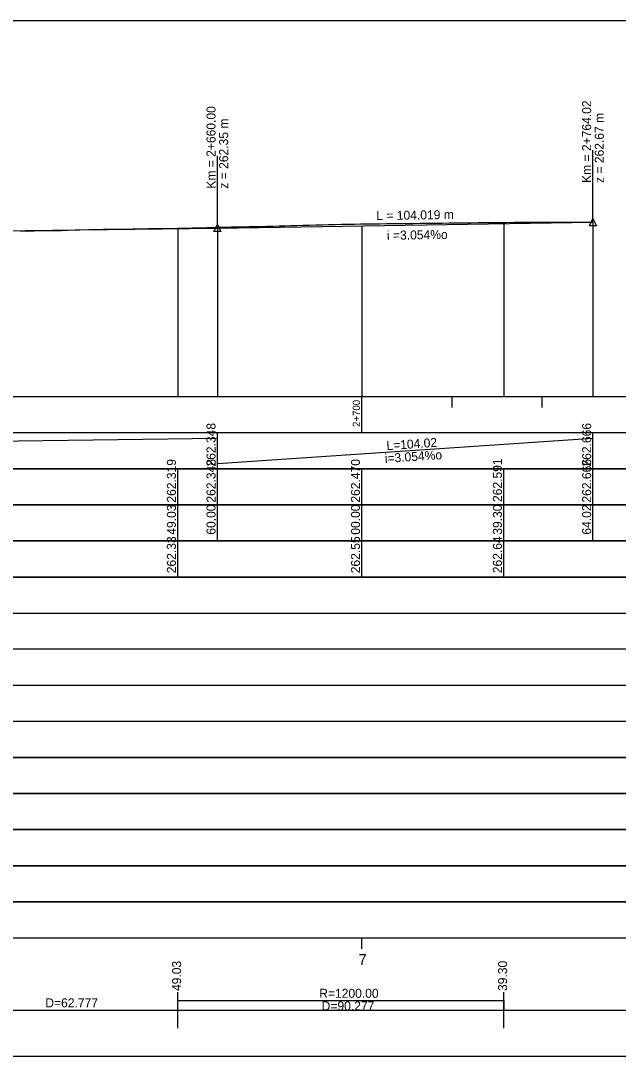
# Model space of a CAD drawing. Extents: x 6445630 to 6518227, y 5499240 to 5511716.
# Drawn here: x 6453136.8 to 6453302.2, y 5505473.3 to 5505760.3 of the extents above; entities that cross this region are included whole.
import ezdxf

# ---------------------------------------------------------------- set-up
doc = ezdxf.new("R2010")
doc.units = 0
for name, color, linetype in [('TOR_PROF-opisy pomocnicze', 7, 'Continuous'), ('TOR_PROF-tabelka-geometria T1', 7, 'Continuous'), ('TOR_PROF-tabelka-kilometracja', 7, 'Continuous'), ('TOR_PROF-tabelka-odleglosci T1', 7, 'Continuous'), ('TOR_PROF-tabelka-pochylenia proj T1', 7, 'Continuous'), ('TOR_PROF-tabelka-rodzaj rowu T1', 7, 'Continuous'), ('TOR_PROF-tabelka-rowyT1', 7, 'Continuous'), ('TOR_PROF-tabelka-rurociagi T1', 7, 'Continuous'), ('TOR_PROF-tabelka-rzedne istn T1', 7, 'Continuous'), ('TOR_PROF-tabelka-rzedne proj T1', 7, 'Continuous'), ('TOR_PROF-tabelka-teren istniejacy T1', 7, 'Continuous'), ('TOR_PROF-tabelka-warstwa ochronna T1', 7, 'Continuous'), ('TOR_PROF-tor istniejacy T2', 7, 'Continuous'), ('TOR_PROF-tor projektowany', 7, 'Continuous'), ('TOR_PROF-uklad odniesienia', 7, 'Continuous'), ('TOR_PROF-warstwa ochronna', 7, 'Continuous'), ('TOR_RAMKI-MASKA WYCIECIA', 7, 'Continuous')]:
    doc.layers.add(name, color=color, linetype=linetype)

msp = doc.modelspace()

# ---------------------------------------------------------------- linework, layer by layer
at = {"layer": 'TOR_PROF-opisy pomocnicze'}
for p, q in [((6453191.21, 5505702.89), (6453191.21, 5505722.89)), ((6453295.23, 5505704.48), (6453295.23, 5505724.48))]:
    msp.add_line(p, q, dxfattribs=at)
for points in [[(6453295.23, 5505705.48), (6453296.23, 5505703.48), (6453294.23, 5505703.48)], [(6453191.21, 5505703.89), (6453192.21, 5505701.89), (6453190.21, 5505701.89)]]:
    msp.add_lwpolyline(points, close=True, dxfattribs=at)
at = {"layer": 'TOR_PROF-tabelka-geometria T1'}
for points in [[(6453180.24, 5505481.15), (6453180.24, 5505491.15)], [(6453270.52, 5505481.15), (6453270.52, 5505491.15)], [(6452396.47, 5505479.99), (6452461.28, 5505479.99), (6452461.27, 5505486.15), (6452523.83, 5505486.15), (6452523.83, 5505486.15), (6452583.83, 5505483.48), (6452583.83, 5505483.48), (6452667.79, 5505483.48), (6452667.79, 5505483.48), (6452727.79, 5505486.15), (6452727.79, 5505486.15), (6452779.05, 5505486.15), (6452779.05, 5505486.15), (6452879.05, 5505483.48), (6452879.05, 5505483.48), (6453017.46, 5505483.48), (6453017.46, 5505483.48), (6453117.46, 5505486.15), (6453117.46, 5505486.15), (6453180.24, 5505486.15), (6453180.24, 5505488.81), (6453270.52, 5505488.81), (6453270.52, 5505486.15), (6453440.82, 5505486.15)], [(6452331.21, 5505486.15), (6453531.21, 5505486.15)]]:
    msp.add_lwpolyline(points, dxfattribs=at)
at = {"layer": 'TOR_PROF-tabelka-kilometracja'}
msp.add_lwpolyline([(6453231.21, 5505503.15), (6453231.21, 5505506.15)], dxfattribs=at)
at = {"layer": 'TOR_PROF-tabelka-odleglosci T1'}
msp.add_lwpolyline([(6452331.21, 5505616.15), (6453531.21, 5505616.15), (6453531.21, 5505626.15), (6452331.21, 5505626.15)], close=True, dxfattribs=at)
for points in [[(6453180.24, 5505616.15), (6453180.24, 5505626.15)], [(6453191.21, 5505616.15), (6453191.21, 5505626.15)], [(6453231.21, 5505616.15), (6453231.21, 5505626.15)], [(6453270.52, 5505616.15), (6453270.52, 5505626.15)], [(6453295.23, 5505616.15), (6453295.23, 5505626.15)]]:
    msp.add_lwpolyline(points, dxfattribs=at)
at = {"layer": 'TOR_PROF-tabelka-pochylenia proj T1'}
msp.add_lwpolyline([(6452331.21, 5505636.15), (6453531.21, 5505636.15), (6453531.21, 5505646.15), (6452331.21, 5505646.15)], close=True, dxfattribs=at)
for points in [[(6452667.21, 5505637.65), (6453191.21, 5505644.65)], [(6453191.21, 5505636.15), (6453191.21, 5505646.15)], [(6453191.21, 5505637.65), (6453295.23, 5505644.65)], [(6453295.23, 5505636.15), (6453295.23, 5505646.15)]]:
    msp.add_lwpolyline(points, dxfattribs=at)
at = {"layer": 'TOR_PROF-tabelka-rodzaj rowu T1'}
for points in [[(6452331.21, 5505576.15), (6453531.21, 5505576.15), (6453531.21, 5505586.15), (6452331.21, 5505586.15)], [(6452331.21, 5505556.15), (6453531.21, 5505556.15), (6453531.21, 5505566.15), (6452331.21, 5505566.15)], [(6452331.21, 5505546.15), (6453531.21, 5505546.15), (6453531.21, 5505556.15), (6452331.21, 5505556.15)]]:
    msp.add_lwpolyline(points, close=True, dxfattribs=at)
at = {"layer": 'TOR_PROF-tabelka-rowyT1'}
msp.add_lwpolyline([(6452331.21, 5505576.15), (6453531.21, 5505576.15), (6453531.21, 5505586.15), (6452331.21, 5505586.15)], close=True, dxfattribs=at)
at = {"layer": 'TOR_PROF-tabelka-rurociagi T1'}
for points in [[(6452331.21, 5505556.15), (6453531.21, 5505556.15), (6453531.21, 5505566.15), (6452331.21, 5505566.15)], [(6452331.21, 5505536.15), (6453531.21, 5505536.15), (6453531.21, 5505546.15), (6452331.21, 5505546.15)], [(6452331.21, 5505526.15), (6453531.21, 5505526.15), (6453531.21, 5505536.15), (6452331.21, 5505536.15)]]:
    msp.add_lwpolyline(points, close=True, dxfattribs=at)
at = {"layer": 'TOR_PROF-tabelka-rzedne istn T1'}
msp.add_lwpolyline([(6452331.21, 5505606.15), (6453531.21, 5505606.15), (6453531.21, 5505616.15), (6452331.21, 5505616.15)], close=True, dxfattribs=at)
for points in [[(6453180.24, 5505606.15), (6453180.24, 5505616.15)], [(6453231.21, 5505606.15), (6453231.21, 5505616.15)], [(6453270.52, 5505606.15), (6453270.52, 5505616.15)]]:
    msp.add_lwpolyline(points, dxfattribs=at)
at = {"layer": 'TOR_PROF-tabelka-rzedne proj T1'}
msp.add_lwpolyline([(6452331.21, 5505626.15), (6453531.21, 5505626.15), (6453531.21, 5505636.15), (6452331.21, 5505636.15)], close=True, dxfattribs=at)
for points in [[(6453180.24, 5505626.15), (6453180.24, 5505636.15)], [(6453191.21, 5505626.15), (6453191.21, 5505636.15)], [(6453231.21, 5505626.15), (6453231.21, 5505636.15)], [(6453270.52, 5505626.15), (6453270.52, 5505636.15)], [(6453295.23, 5505626.15), (6453295.23, 5505636.15)]]:
    msp.add_lwpolyline(points, dxfattribs=at)
at = {"layer": 'TOR_PROF-tabelka-teren istniejacy T1'}
for points in [[(6452331.21, 5505596.15), (6453531.21, 5505596.15), (6453531.21, 5505606.15), (6452331.21, 5505606.15)], [(6452331.21, 5505576.15), (6453531.21, 5505576.15), (6453531.21, 5505586.15), (6452331.21, 5505586.15)]]:
    msp.add_lwpolyline(points, close=True, dxfattribs=at)
at = {"layer": 'TOR_PROF-tabelka-warstwa ochronna T1'}
msp.add_lwpolyline([(6452331.21, 5505516.15), (6453531.21, 5505516.15), (6453531.21, 5505526.15), (6452331.21, 5505526.15)], close=True, dxfattribs=at)
at = {"layer": 'TOR_PROF-tor istniejacy T2'}
msp.add_lwpolyline([(6453295.24, 5505704.5), (6453290.58, 5505704.46), (6453282.97, 5505704.42), (6453275.37, 5505704.4), (6453273.37, 5505704.38), (6453271.38, 5505704.36), (6453269.38, 5505704.34), (6453267.39, 5505704.32), (6453265.39, 5505704.3), (6453263.4, 5505704.28), (6453261.41, 5505704.26), (6453259.41, 5505704.24), (6453257.42, 5505704.22), (6453255.42, 5505704.2), (6453253.43, 5505704.17), (6453251.43, 5505704.15), (6453249.44, 5505704.12), (6453247.44, 5505704.1), (6453245.45, 5505704.07), (6453243.46, 5505704.05), (6453241.67, 5505704.04), (6453239.88, 5505704.02), (6453238.1, 5505704.01), (6453236.31, 5505703.99), (6453234.53, 5505703.97), (6453232.74, 5505703.94), (6453230.95, 5505703.92), (6453229.17, 5505703.89), (6453227.38, 5505703.85), (6453225.6, 5505703.82), (6453223.81, 5505703.78), (6453222.03, 5505703.74), (6453220.24, 5505703.7), (6453218.45, 5505703.65), (6453216.67, 5505703.6), (6453214.88, 5505703.55), (6453213.23, 5505703.5), (6453211.57, 5505703.46), (6453209.92, 5505703.42), (6453208.26, 5505703.38), (6453206.61, 5505703.34), (6453204.95, 5505703.3), (6453203.3, 5505703.26), (6453201.64, 5505703.23), (6453199.98, 5505703.19), (6453198.33, 5505703.15), (6453196.67, 5505703.12), (6453195.02, 5505703.08), (6453193.36, 5505703.05), (6453191.71, 5505703.01), (6453190.05, 5505702.98), (6453188.4, 5505702.95), (6453184.3, 5505702.86), (6453180.2, 5505702.78), (6453176.1, 5505702.7), (6453172, 5505702.63), (6453167.9, 5505702.56), (6453163.8, 5505702.5), (6453159.7, 5505702.45), (6453155.6, 5505702.4), (6453151.81, 5505702.26), (6453148.03, 5505702.15), (6453144.24, 5505702.06), (6453140.46, 5505702), (6453136.67, 5505701.96)], dxfattribs=at)
at = {"layer": 'TOR_PROF-tor projektowany'}
for p, q in [((6452667.21, 5505695.81), (6453191.21, 5505702.89)), ((6453191.21, 5505702.89), (6453295.23, 5505704.48))]:
    msp.add_line(p, q, dxfattribs=at)
for points in [[(6453180.24, 5505702.74), (6453180.24, 5505661.15), (6453180.24, 5505656.15), (6453180.24, 5505656.15)], [(6453180.24, 5505702.74), (6453180.24, 5505661.15), (6453180.24, 5505656.15), (6453180.24, 5505656.15)], [(6453191.21, 5505702.89), (6453191.21, 5505661.15), (6453191.21, 5505656.15), (6453191.21, 5505656.15)], [(6453191.21, 5505702.89), (6453191.21, 5505661.15), (6453191.21, 5505656.15), (6453191.21, 5505656.15)], [(6453191.21, 5505702.89), (6453191.21, 5505661.15), (6453191.21, 5505656.15), (6453191.21, 5505656.15)], [(6453191.21, 5505702.89), (6453191.21, 5505661.15), (6453191.21, 5505656.15), (6453191.21, 5505656.15)], [(6453231.21, 5505703.5), (6453231.21, 5505661.15), (6453231.21, 5505656.15), (6453231.21, 5505656.15)], [(6453231.21, 5505703.5), (6453231.21, 5505661.15), (6453231.21, 5505656.15), (6453231.21, 5505656.15)], [(6453270.52, 5505704.1), (6453270.52, 5505661.15), (6453270.52, 5505656.15), (6453270.52, 5505656.15)], [(6453270.52, 5505704.1), (6453270.52, 5505661.15), (6453270.52, 5505656.15), (6453270.52, 5505656.15)], [(6453295.23, 5505704.48), (6453295.23, 5505661.15), (6453295.23, 5505656.15), (6453295.23, 5505656.15)], [(6453295.23, 5505704.48), (6453295.23, 5505661.15), (6453295.23, 5505656.15), (6453295.23, 5505656.15)], [(6453295.23, 5505704.48), (6453295.23, 5505661.15), (6453295.23, 5505656.15), (6453295.23, 5505656.15)], [(6453295.23, 5505704.48), (6453295.23, 5505661.15), (6453295.23, 5505656.15), (6453295.23, 5505656.15)]]:
    msp.add_lwpolyline(points, dxfattribs=at)
at = {"layer": 'TOR_PROF-uklad odniesienia'}
for p, q in [((6452331.21, 5505656.15), (6453531.21, 5505656.15)), ((6453231.21, 5505646.15), (6453231.21, 5505656.15)), ((6453256.21, 5505653.15), (6453256.21, 5505656.15)), ((6453281.21, 5505653.15), (6453281.21, 5505656.15))]:
    msp.add_line(p, q, dxfattribs=at)
at = {"layer": 'TOR_PROF-warstwa ochronna'}
msp.add_lwpolyline([(6452331.21, 5505506.15), (6453531.21, 5505506.15), (6453531.21, 5505516.15), (6452331.21, 5505516.15)], close=True, dxfattribs=at)
at = {"layer": 'TOR_RAMKI-MASKA WYCIECIA'}
msp.add_lwpolyline([(6452249.83, 5505473.34), (6453559.83, 5505473.34), (6453559.83, 5505760.34), (6452249.83, 5505760.34)], close=True, dxfattribs=at)

# ---------------------------------------------------------------- texts
at = {"layer": 'TOR_PROF-opisy pomocnicze'}
for s, rotation, p in [('Km = 2+660.00', 90, (6453190.71, 5505713.79)), ('Km = 2+764.02', 90, (6453294.73, 5505715.38)), ('z = 262.67 m', 90, (6453298.23, 5505715.38)), ('z = 262.35 m', 90, (6453194.21, 5505713.79)), ('L = 104.019 m', 0.8749, (6453235.25, 5505705.06)), ('  i =3.054%o', 0.8749, (6453236.34, 5505699.58))]:
    msp.add_text(s, height=2.5, rotation=rotation, dxfattribs=at).set_placement(p)
at = {"layer": 'TOR_PROF-tabelka-geometria T1'}
for s, p in [('D=62.777', (6453143.57, 5505486.9)), ('R=1200.00', (6453219.42, 5505489.54)), ('D=90.277', (6453220.1, 5505486.04))]:
    msp.add_text(s, height=2.5, dxfattribs=at).set_placement(p)
at = {"layer": 'TOR_PROF-tabelka-kilometracja'}
msp.add_text('7', height=3, dxfattribs=at).set_placement((6453230.32, 5505498.65))
at = {"layer": 'TOR_PROF-tabelka-odleglosci T1'}
for s, p in [('49.03', (6453179.74, 5505617.89)), ('60.00', (6453190.71, 5505617.89)), ('00.00', (6453230.71, 5505617.89)), ('39.30', (6453270.02, 5505617.89)), ('64.02', (6453294.73, 5505617.91)), ('49.03', (6453181.18, 5505491.43)), ('39.30', (6453271.45, 5505491.44))]:
    msp.add_text(s, height=2.5, rotation=90, dxfattribs=at).set_placement(p)
at = {"layer": 'TOR_PROF-tabelka-pochylenia proj T1'}
for s, rotation, p in [('262.348', 90, (6453190.71, 5505636.78)), ('262.666', 90, (6453294.73, 5505636.78)), ('L=104.02', 3.8499, (6453238.13, 5505641.31)), ('i=3.054%o', 3.8499, (6453237.66, 5505637.77))]:
    msp.add_text(s, height=2.5, rotation=rotation, dxfattribs=at).set_placement(p)
at = {"layer": 'TOR_PROF-tabelka-rzedne istn T1'}
for s, p in [('262.33', (6453179.74, 5505607.21)), ('262.55', (6453230.71, 5505607.21)), ('262.64', (6453270.02, 5505607.22))]:
    msp.add_text(s, height=2.5, rotation=90, dxfattribs=at).set_placement(p)
at = {"layer": 'TOR_PROF-tabelka-rzedne proj T1'}
for s, p in [('262.319', (6453179.74, 5505626.78)), ('262.348', (6453190.71, 5505626.78)), ('262.470', (6453230.71, 5505626.78)), ('262.591', (6453270.02, 5505626.95)), ('262.666', (6453294.73, 5505626.78))]:
    msp.add_text(s, height=2.5, rotation=90, dxfattribs=at).set_placement(p)
at = {"layer": 'TOR_PROF-uklad odniesienia'}
msp.add_text('2+700', height=2, rotation=90, dxfattribs=at).set_placement((6453230.71, 5505647.75))

doc.saveas('drawing.dxf')
